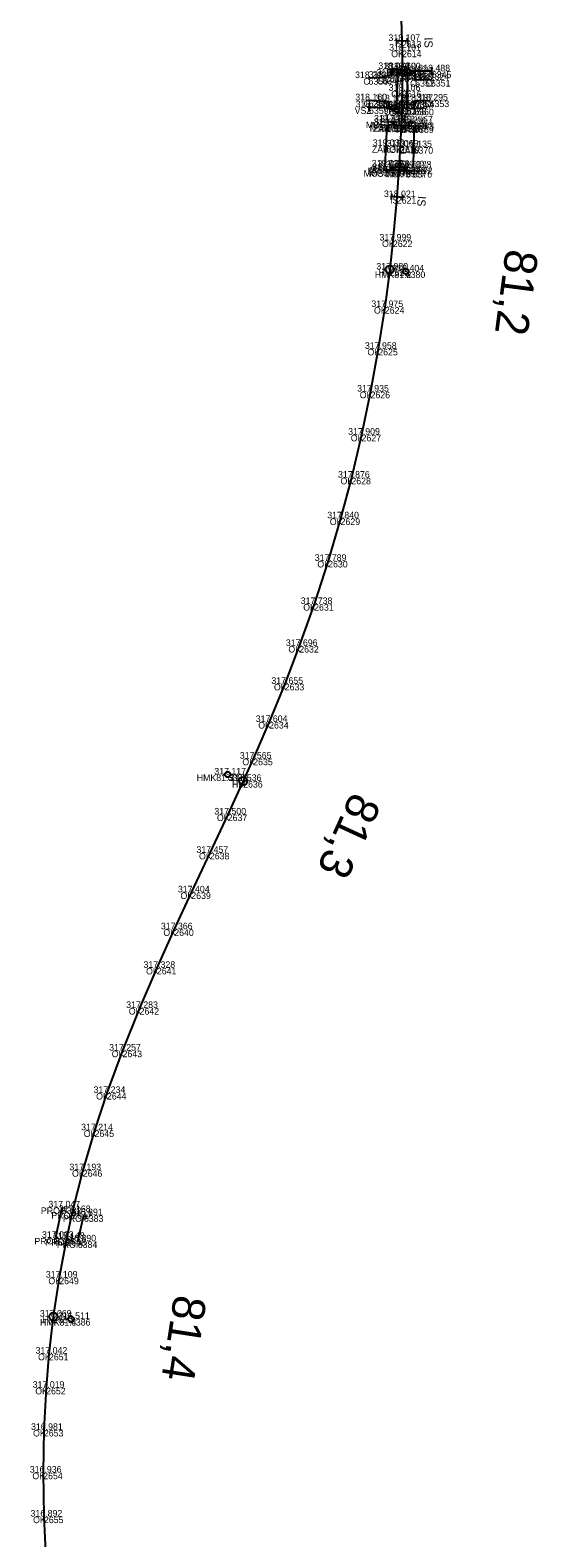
# Model space of a CAD drawing. Extents: x -621782 to -610392, y -1141853 to -1122321.
# Drawn here: x -613895.7 to -613802.8, y -1131273.8 to -1130998.2 of the extents above; entities that cross this region are included whole.
import ezdxf

# ---------------------------------------------------------------- set-up
doc = ezdxf.new("R2010")
doc.units = 0
for name, color, linetype in [('Vrstva 1', 7, 'Continuous'), ('Vrstva 17', 7, 'Continuous'), ('Vrstva 18', 7, 'Continuous'), ('Vrstva 19', 7, 'Continuous'), ('Vrstva 3', 7, 'Continuous'), ('Vrstva 4', 7, 'Continuous'), ('Vrstva 51', 7, 'Continuous'), ('Vrstva 60', 7, 'Continuous'), ('Vrstva 61', 7, 'Continuous'), ('Vrstva 62', 7, 'Continuous'), ('Vrstva 7', 7, 'Continuous')]:
    doc.layers.add(name, color=color, linetype=linetype)

msp = doc.modelspace()

# ---------------------------------------------------------------- linework, layer by layer
at = {"layer": 'Vrstva 1'}
msp.add_lwpolyline([(-613827.82, -1130996.25), (-613827.71, -1131000.22), (-613827.67, -1131001.98), (-613827.63, -1131005.39), (-613827.67, -1131009.32), (-613827.73, -1131012.39), (-613827.84, -1131015.6), (-613828.02, -1131019.5), (-613828.24, -1131023.38), (-613828.63, -1131028.75), (-613829.34, -1131036.69), (-613829.92, -1131041.99), (-613830.82, -1131048.85), (-613832.02, -1131056.48), (-613833.43, -1131064.3), (-613835.07, -1131072.18), (-613836.94, -1131080.04), (-613838.91, -1131087.47), (-613841.19, -1131095.24), (-613843.76, -1131103.13), (-613846.48, -1131110.79), (-613849.13, -1131117.71), (-613851.99, -1131124.68), (-613854.9, -1131131.39), (-613856.74, -1131135.47), (-613859.56, -1131141.59), (-613862.83, -1131148.6), (-613866.23, -1131155.83), (-613869.35, -1131162.58), (-613872.53, -1131169.62), (-613875.69, -1131176.96), (-613878.81, -1131184.75), (-613881.66, -1131192.49), (-613883.93, -1131199.32), (-613886.08, -1131206.6), (-613888.01, -1131214.26), (-613889.08, -1131219.17), (-613890.39, -1131226.24), (-613891.49, -1131233.37), (-613892.27, -1131240.14), (-613892.79, -1131246.37), (-613893.2, -1131254.07), (-613893.33, -1131261.88), (-613893.19, -1131269.91), (-613892.85, -1131277.7)], dxfattribs=at)
at = {"layer": 'Vrstva 17'}
for points in [[(-613830.76, -1131023.15), (-613830.58, -1131019.41), (-613830.41, -1131015.61)], [(-613825.46, -1131015.82), (-613825.55, -1131019.62), (-613825.65, -1131023.34)]]:
    msp.add_lwpolyline(points, dxfattribs=at)
at = {"layer": 'Vrstva 18'}
for points in [[(-613825.4, -1131015.14), (-613826.54, -1131015.12), (-613826.58, -1131015.74), (-613829.27, -1131015.62), (-613829.25, -1131015.02), (-613830.34, -1131014.94)], [(-613830.76, -1131023.82), (-613829.66, -1131023.84), (-613829.64, -1131023.24), (-613826.93, -1131023.29), (-613826.94, -1131023.94), (-613825.74, -1131023.97)]]:
    msp.add_lwpolyline(points, dxfattribs=at)
at = {"layer": 'Vrstva 19'}
for p, q in [((-613889.92, -1131213.41), (-613891.1, -1131218.97)), ((-613887, -1131219.62), (-613885.88, -1131214.85))]:
    msp.add_line(p, q, dxfattribs=at)
at = {"layer": 'Vrstva 3'}
for p, q in [((-613828.72, -1130999.74), (-613828.7, -1131000.74)), ((-613826.71, -1131000.2), (-613828.71, -1131000.24)), ((-613826.72, -1130999.7), (-613826.7, -1131000.7)), ((-613829.58, -1131028.16), (-613829.67, -1131029.16)), ((-613827.63, -1131028.84), (-613829.62, -1131028.66)), ((-613827.59, -1131028.34), (-613827.67, -1131029.34))]:
    msp.add_line(p, q, dxfattribs=at)
at = {"layer": 'Vrstva 4'}
for p, q in [((-613826.9, -1131005.92), (-613827.24, -1131005.57)), ((-613822.24, -1131006.53), (-613822.22, -1131004.98)), ((-613833.68, -1131011.57), (-613833.74, -1131013.12)), ((-613829.04, -1131012.3), (-613828.71, -1131012.66))]:
    msp.add_line(p, q, dxfattribs=at)
for points in [[(-613822.23, -1131005.76), (-613825.71, -1131005.72), (-613827.73, -1131006.69), (-613827.71, -1131004.69), (-613825.71, -1131005.72)], [(-613827.63, -1131005.39), (-613827.67, -1131009.32), (-613827.73, -1131012.39)], [(-613833.71, -1131012.34), (-613830.24, -1131012.46), (-613828.2, -1131011.55), (-613828.26, -1131013.55), (-613830.24, -1131012.46)]]:
    msp.add_lwpolyline(points, dxfattribs=at)
for centre in [(-613827.07, -1131005.74), (-613828.88, -1131012.48)]:
    msp.add_circle(centre, 0.248, dxfattribs=at)
at = {"layer": 'Vrstva 51'}
for points in [[(-613833.77, -1131011.06), (-613830.13, -1131011.25), (-613830.03, -1131012.58), (-613828.63, -1131012.42), (-613828.47, -1131005.37), (-613829.57, -1131005.35), (-613829.89, -1131006.55), (-613831.31, -1131006.92), (-613833.81, -1131007)], [(-613822.39, -1131007.34), (-613825.27, -1131007.36), (-613825.25, -1131006.16), (-613826.75, -1131006), (-613826.78, -1131012.49), (-613825.43, -1131012.59), (-613825.36, -1131011.18), (-613822.62, -1131011.1)]]:
    msp.add_lwpolyline(points, dxfattribs=at)
at = {"layer": 'Vrstva 60'}
for p, q in [((-613827.71, -1131000.22), (-613827.71, -1131000.22)), ((-613827.67, -1131001.98), (-613827.67, -1131001.98)), ((-613831.31, -1131006.92), (-613831.31, -1131006.92)), ((-613829.89, -1131006.55), (-613829.89, -1131006.55)), ((-613829.57, -1131005.35), (-613829.57, -1131005.35)), ((-613828.47, -1131005.37), (-613828.47, -1131005.37)), ((-613827.63, -1131005.39), (-613827.63, -1131005.39)), ((-613826.75, -1131006), (-613826.75, -1131006)), ((-613825.25, -1131006.16), (-613825.25, -1131006.16)), ((-613822.23, -1131005.76), (-613822.23, -1131005.76)), ((-613833.81, -1131007), (-613833.81, -1131007)), ((-613827.67, -1131009.32), (-613827.67, -1131009.32)), ((-613825.27, -1131007.36), (-613825.27, -1131007.36)), ((-613822.39, -1131007.34), (-613822.39, -1131007.34)), ((-613833.77, -1131011.06), (-613833.77, -1131011.06)), ((-613833.71, -1131012.34), (-613833.71, -1131012.34)), ((-613830.13, -1131011.25), (-613830.13, -1131011.25)), ((-613828.63, -1131012.42), (-613828.63, -1131012.42)), ((-613827.73, -1131012.39), (-613827.73, -1131012.39)), ((-613826.78, -1131012.49), (-613826.78, -1131012.49)), ((-613825.36, -1131011.18), (-613825.36, -1131011.18)), ((-613822.62, -1131011.1), (-613822.62, -1131011.1)), ((-613830.34, -1131014.94), (-613830.34, -1131014.94)), ((-613830.03, -1131012.58), (-613830.03, -1131012.58)), ((-613829.25, -1131015.02), (-613829.25, -1131015.02)), ((-613826.54, -1131015.12), (-613826.54, -1131015.12)), ((-613825.43, -1131012.59), (-613825.43, -1131012.59)), ((-613825.4, -1131015.14), (-613825.4, -1131015.14)), ((-613830.41, -1131015.61), (-613830.41, -1131015.61)), ((-613829.27, -1131015.62), (-613829.27, -1131015.62)), ((-613827.84, -1131015.6), (-613827.84, -1131015.6)), ((-613826.58, -1131015.74), (-613826.58, -1131015.74)), ((-613825.46, -1131015.82), (-613825.46, -1131015.82)), ((-613830.58, -1131019.41), (-613830.58, -1131019.41)), ((-613828.02, -1131019.5), (-613828.02, -1131019.5)), ((-613825.55, -1131019.62), (-613825.55, -1131019.62)), ((-613830.76, -1131023.15), (-613830.76, -1131023.15)), ((-613829.64, -1131023.24), (-613829.64, -1131023.24)), ((-613828.24, -1131023.38), (-613828.24, -1131023.38)), ((-613826.93, -1131023.29), (-613826.93, -1131023.29)), ((-613825.65, -1131023.34), (-613825.65, -1131023.34)), ((-613830.76, -1131023.82), (-613830.76, -1131023.82)), ((-613829.66, -1131023.84), (-613829.66, -1131023.84)), ((-613826.94, -1131023.94), (-613826.94, -1131023.94)), ((-613825.74, -1131023.97), (-613825.74, -1131023.97)), ((-613828.63, -1131028.75), (-613828.63, -1131028.75)), ((-613829.34, -1131036.69), (-613829.34, -1131036.69)), ((-613829.92, -1131041.99), (-613829.92, -1131041.99)), ((-613826.99, -1131042.34), (-613826.99, -1131042.34)), ((-613830.82, -1131048.85), (-613830.82, -1131048.85)), ((-613832.02, -1131056.48), (-613832.02, -1131056.48)), ((-613833.43, -1131064.3), (-613833.43, -1131064.3)), ((-613835.07, -1131072.18), (-613835.07, -1131072.18)), ((-613836.94, -1131080.04), (-613836.94, -1131080.04)), ((-613838.91, -1131087.47), (-613838.91, -1131087.47)), ((-613841.19, -1131095.24), (-613841.19, -1131095.24)), ((-613843.76, -1131103.13), (-613843.76, -1131103.13)), ((-613846.48, -1131110.79), (-613846.48, -1131110.79)), ((-613849.13, -1131117.71), (-613849.13, -1131117.71)), ((-613851.99, -1131124.68), (-613851.99, -1131124.68)), ((-613854.9, -1131131.39), (-613854.9, -1131131.39)), ((-613859.57, -1131134.28), (-613859.57, -1131134.28)), ((-613856.74, -1131135.47), (-613856.74, -1131135.47)), ((-613859.56, -1131141.59), (-613859.56, -1131141.59)), ((-613862.83, -1131148.6), (-613862.83, -1131148.6)), ((-613866.23, -1131155.83), (-613866.23, -1131155.83)), ((-613869.35, -1131162.58), (-613869.35, -1131162.58)), ((-613872.53, -1131169.62), (-613872.53, -1131169.62)), ((-613875.69, -1131176.96), (-613875.69, -1131176.96)), ((-613878.81, -1131184.75), (-613878.81, -1131184.75)), ((-613881.66, -1131192.49), (-613881.66, -1131192.49)), ((-613883.93, -1131199.32), (-613883.93, -1131199.32)), ((-613886.08, -1131206.6), (-613886.08, -1131206.6)), ((-613889.92, -1131213.41), (-613889.92, -1131213.41)), ((-613888.01, -1131214.26), (-613888.01, -1131214.26)), ((-613885.88, -1131214.85), (-613885.88, -1131214.85)), ((-613891.1, -1131218.97), (-613891.1, -1131218.97)), ((-613889.08, -1131219.17), (-613889.08, -1131219.17)), ((-613887, -1131219.62), (-613887, -1131219.62)), ((-613890.39, -1131226.24), (-613890.39, -1131226.24)), ((-613891.49, -1131233.37), (-613891.49, -1131233.37)), ((-613888.25, -1131233.8), (-613888.25, -1131233.8)), ((-613892.27, -1131240.14), (-613892.27, -1131240.14)), ((-613892.79, -1131246.37), (-613892.79, -1131246.37)), ((-613893.2, -1131254.07), (-613893.2, -1131254.07)), ((-613893.33, -1131261.88), (-613893.33, -1131261.88)), ((-613893.19, -1131269.91), (-613893.19, -1131269.91))]:
    msp.add_line(p, q, dxfattribs=at)
at = {"layer": 'Vrstva 7'}
for p, q in [((-613826.99, -1131042.29), (-613827, -1131042.39)), ((-613859.55, -1131134.24), (-613859.59, -1131134.33)), ((-613888.24, -1131233.75), (-613888.26, -1131233.85))]:
    msp.add_line(p, q, dxfattribs=at)
for centre, radius in [((-613829.92, -1131041.99), 0.75), ((-613826.99, -1131042.34), 0.5), ((-613859.57, -1131134.28), 0.5), ((-613856.74, -1131135.47), 0.75), ((-613891.49, -1131233.37), 0.75), ((-613888.25, -1131233.8), 0.5)]:
    msp.add_circle(centre, radius, dxfattribs=at)

# ---------------------------------------------------------------- texts
at = {"layer": 'Vrstva 3'}
for rotation, p in [(271.1711, (-613823.6, -1130999.58)), (264.8479, (-613824.75, -1131028.5))]:
    msp.add_text('IS', height=1.5, rotation=rotation, dxfattribs=at).set_placement(p)
at = {"layer": 'Vrstva 60'}
for s, p in [('2613', (-613827.71, -1131001.42)), ('2614', (-613827.67, -1131003.18)), ('6350', (-613833.81, -1131008.2)), ('6349', (-613831.31, -1131008.11)), ('6348', (-613829.89, -1131007.75)), ('6343', (-613829.57, -1131006.55)), ('6344', (-613828.47, -1131006.57)), ('2615', (-613827.63, -1131006.59)), ('6346', (-613826.75, -1131007.2)), ('6347', (-613825.25, -1131007.36)), ('6345', (-613822.23, -1131006.96)), ('2616', (-613827.67, -1131010.52)), ('6352', (-613825.27, -1131008.56)), ('6351', (-613822.39, -1131008.54)), ('6355', (-613833.77, -1131012.26)), ('6359', (-613833.71, -1131013.54)), ('6356', (-613830.13, -1131012.45)), ('6357', (-613828.63, -1131013.62)), ('2617', (-613827.73, -1131013.59)), ('6358', (-613826.78, -1131013.69)), ('6354', (-613825.36, -1131012.38)), ('6353', (-613822.62, -1131012.3)), ('6362', (-613830.34, -1131016.14)), ('6361', (-613830.03, -1131013.78)), ('6364', (-613829.25, -1131016.22)), ('6365', (-613826.54, -1131016.32)), ('6360', (-613825.43, -1131013.79)), ('6363', (-613825.4, -1131016.34)), ('6368', (-613830.41, -1131016.81)), ('6366', (-613829.27, -1131016.82)), ('2618', (-613827.84, -1131016.8)), ('6367', (-613826.58, -1131016.94)), ('6369', (-613825.46, -1131017.02)), ('6371', (-613830.58, -1131020.61)), ('2619', (-613828.02, -1131020.7)), ('6370', (-613825.55, -1131020.82)), ('6374', (-613830.76, -1131024.35)), ('6375', (-613829.64, -1131024.44)), ('2620', (-613828.24, -1131024.58)), ('6373', (-613826.93, -1131024.49)), ('6372', (-613825.65, -1131024.54)), ('6379', (-613830.76, -1131025.02)), ('6378', (-613829.66, -1131025.04)), ('6377', (-613826.94, -1131025.14)), ('6376', (-613825.74, -1131025.17)), ('2621', (-613828.63, -1131029.95)), ('2622', (-613829.34, -1131037.89)), ('2623', (-613829.92, -1131043.19)), ('6380', (-613826.99, -1131043.54)), ('2624', (-613830.82, -1131050.05)), ('2625', (-613832.02, -1131057.68)), ('2626', (-613833.43, -1131065.51)), ('2627', (-613835.07, -1131073.38)), ('2628', (-613836.94, -1131081.24)), ('2629', (-613838.91, -1131088.67)), ('2630', (-613841.19, -1131096.44)), ('2631', (-613843.76, -1131104.33)), ('2632', (-613846.48, -1131111.99)), ('2633', (-613849.13, -1131118.91)), ('2634', (-613851.99, -1131125.88)), ('2635', (-613854.9, -1131132.59)), ('6381', (-613859.57, -1131135.48)), ('2636', (-613856.74, -1131136.67)), ('2637', (-613859.56, -1131142.79)), ('2638', (-613862.83, -1131149.8)), ('2639', (-613866.23, -1131157.03)), ('2640', (-613869.35, -1131163.78)), ('2641', (-613872.53, -1131170.82)), ('2642', (-613875.69, -1131178.16)), ('2643', (-613878.81, -1131185.95)), ('2644', (-613881.66, -1131193.69)), ('2645', (-613883.93, -1131200.52)), ('2646', (-613886.08, -1131207.8)), ('6382', (-613889.92, -1131214.61)), ('2647', (-613888.01, -1131215.46)), ('6383', (-613885.88, -1131216.05)), ('6385', (-613891.1, -1131220.17)), ('2648', (-613889.08, -1131220.37)), ('6384', (-613887, -1131220.82)), ('2649', (-613890.39, -1131227.44)), ('2650', (-613891.49, -1131234.57)), ('6386', (-613888.25, -1131235)), ('2651', (-613892.27, -1131241.34)), ('2652', (-613892.79, -1131247.57)), ('2653', (-613893.2, -1131255.27)), ('2654', (-613893.33, -1131263.08)), ('2655', (-613893.19, -1131271.11))]:
    msp.add_text(s, height=1.2, dxfattribs=at).set_placement(p)
at = {"layer": 'Vrstva 61'}
for s, p in [('318.107', (-613830.16, -1131000.22)), ('318.101', (-613830.03, -1131001.98)), ('318.072', (-613832.01, -1131005.35)), ('318.060', (-613830.92, -1131005.37)), ('318.100', (-613830.08, -1131005.39)), ('318.203', (-613836.27, -1131007)), ('318.189', (-613833.77, -1131006.92)), ('318.149', (-613832.35, -1131006.55)), ('318.140', (-613829.2, -1131006)), ('318.219', (-613827.72, -1131007.36)), ('318.233', (-613827.7, -1131006.16)), ('318.324', (-613824.84, -1131007.34)), ('318.488', (-613824.69, -1131005.76)), ('318.106', (-613830.12, -1131009.32)), ('318.160', (-613836.22, -1131011.06)), ('318.246', (-613836.17, -1131012.34)), ('318.102', (-613832.58, -1131011.25)), ('318.086', (-613832.48, -1131012.58)), ('318.085', (-613831.08, -1131012.42)), ('318.087', (-613830.19, -1131012.39)), ('318.123', (-613829.23, -1131012.49)), ('318.107', (-613827.88, -1131012.59)), ('318.187', (-613827.81, -1131011.18)), ('318.295', (-613825.08, -1131011.1)), ('319.039', (-613832.86, -1131015.61)), ('317.878', (-613832.8, -1131014.94)), ('317.880', (-613831.7, -1131015.02)), ('317.871', (-613831.62, -1131015.62)), ('318.074', (-613830.29, -1131015.6)), ('317.946', (-613829.03, -1131015.74)), ('317.961', (-613828.9, -1131015.12)), ('319.164', (-613827.91, -1131015.82)), ('317.957', (-613827.85, -1131015.14)), ('319.030', (-613833.04, -1131019.41)), ('318.069', (-613830.48, -1131019.5)), ('319.135', (-613828.01, -1131019.62)), ('319.032', (-613833.21, -1131023.15)), ('317.851', (-613833.11, -1131023.82)), ('317.852', (-613832.1, -1131023.84)), ('317.858', (-613832.09, -1131023.24)), ('318.046', (-613830.69, -1131023.38)), ('317.920', (-613829.39, -1131023.94)), ('317.949', (-613829.38, -1131023.29)), ('317.925', (-613828.2, -1131023.97)), ('319.128', (-613828.1, -1131023.34)), ('318.021', (-613830.98, -1131028.75)), ('317.999', (-613831.8, -1131036.69)), ('317.980', (-613832.37, -1131041.99)), ('318.404', (-613829.44, -1131042.34)), ('317.975', (-613833.28, -1131048.85)), ('317.958', (-613834.47, -1131056.48)), ('317.935', (-613835.89, -1131064.3)), ('317.909', (-613837.53, -1131072.18)), ('317.876', (-613839.39, -1131080.04)), ('317.840', (-613841.36, -1131087.47)), ('317.789', (-613843.64, -1131095.24)), ('317.738', (-613846.22, -1131103.13)), ('317.696', (-613848.93, -1131110.79)), ('317.655', (-613851.58, -1131117.71)), ('317.604', (-613854.44, -1131124.68)), ('317.565', (-613857.36, -1131131.39)), ('317.117', (-613862.02, -1131134.28)), ('317.536', (-613859.2, -1131135.47)), ('317.500', (-613862.01, -1131141.59)), ('317.457', (-613865.29, -1131148.6)), ('317.404', (-613868.68, -1131155.83)), ('317.366', (-613871.8, -1131162.58)), ('317.328', (-613874.98, -1131169.62)), ('317.283', (-613878.14, -1131176.96)), ('317.257', (-613881.26, -1131184.75)), ('317.234', (-613884.11, -1131192.49)), ('317.214', (-613886.38, -1131199.32)), ('317.193', (-613888.53, -1131206.6)), ('317.047', (-613892.37, -1131213.41)), ('317.168', (-613890.46, -1131214.26)), ('316.891', (-613888.24, -1131214.85)), ('317.003', (-613893.55, -1131218.97)), ('317.148', (-613891.53, -1131219.17)), ('316.890', (-613889.45, -1131219.62)), ('317.109', (-613892.85, -1131226.24)), ('317.069', (-613893.94, -1131233.37)), ('316.511', (-613890.61, -1131233.8)), ('317.042', (-613894.72, -1131240.14)), ('317.019', (-613895.24, -1131246.37)), ('316.981', (-613895.55, -1131254.07)), ('316.936', (-613895.78, -1131261.88)), ('316.892', (-613895.64, -1131269.91))]:
    msp.add_text(s, height=1.2, dxfattribs=at).set_placement(p)
at = {"layer": 'Vrstva 62'}
for s, p in [('IS', (-613828.94, -1131001.42)), ('OK', (-613829.66, -1131003.18)), ('C', (-613834.75, -1131008.2)), ('C', (-613832.25, -1131008.11)), ('C', (-613830.83, -1131007.75)), ('C', (-613830.5, -1131006.55)), ('PRJ', (-613830.12, -1131006.59)), ('C', (-613829.41, -1131006.57)), ('C', (-613827.69, -1131007.2)), ('C', (-613826.18, -1131007.36)), ('VSZ', (-613824.87, -1131006.96)), ('OK', (-613829.65, -1131010.52)), ('C', (-613826.2, -1131008.56)), ('C', (-613823.32, -1131008.54)), ('VSZ', (-613836.35, -1131013.54)), ('C', (-613834.7, -1131012.26)), ('C', (-613831.07, -1131012.45)), ('PRJ', (-613830.22, -1131013.59)), ('C', (-613829.56, -1131013.62)), ('C', (-613827.71, -1131013.69)), ('C', (-613826.29, -1131012.38)), ('C', (-613823.56, -1131012.3)), ('MOST', (-613834.29, -1131016.14)), ('MOST', (-613833.19, -1131016.22)), ('C', (-613830.96, -1131013.78)), ('MOST', (-613830.49, -1131016.32)), ('MOST', (-613829.34, -1131016.34)), ('C', (-613826.36, -1131013.79)), ('MOSTBS', (-613833.58, -1131016.8)), ('MOST', (-613833.21, -1131016.82)), ('ZAB', (-613833.01, -1131016.81)), ('MOST', (-613830.52, -1131016.94)), ('ZAB', (-613828.06, -1131017.02)), ('ZAB', (-613833.19, -1131020.61)), ('OK', (-613830.01, -1131020.7)), ('ZAB', (-613828.15, -1131020.82)), ('MOSTBS', (-613833.97, -1131024.58)), ('MOST', (-613833.58, -1131024.44)), ('ZAB', (-613833.36, -1131024.35)), ('MOST', (-613830.87, -1131024.49)), ('ZAB', (-613828.25, -1131024.54)), ('MOST', (-613834.7, -1131025.02)), ('MOST', (-613833.6, -1131025.04)), ('MOST', (-613830.88, -1131025.14)), ('MOST', (-613829.69, -1131025.17)), ('IS', (-613829.85, -1131029.95)), ('OK', (-613831.33, -1131037.89)), ('HMK81.2', (-613832.65, -1131043.54)), ('HM', (-613831.96, -1131043.19)), ('OK', (-613832.81, -1131050.05)), ('OK', (-613834, -1131057.68)), ('OK', (-613835.41, -1131065.51)), ('OK', (-613837.06, -1131073.38)), ('OK', (-613838.93, -1131081.24)), ('OK', (-613840.89, -1131088.67)), ('OK', (-613843.17, -1131096.44)), ('OK', (-613845.75, -1131104.33)), ('OK', (-613848.47, -1131111.99)), ('OK', (-613851.11, -1131118.91)), ('OK', (-613853.98, -1131125.88)), ('OK', (-613856.89, -1131132.59)), ('HMK81.3', (-613865.23, -1131135.48)), ('HM', (-613858.78, -1131136.67)), ('OK', (-613861.54, -1131142.79)), ('OK', (-613864.82, -1131149.8)), ('OK', (-613868.21, -1131157.03)), ('OK', (-613871.34, -1131163.78)), ('OK', (-613874.51, -1131170.82)), ('OK', (-613877.67, -1131178.16)), ('OK', (-613880.79, -1131185.95)), ('OK', (-613883.64, -1131193.69)), ('OK', (-613885.91, -1131200.52)), ('OK', (-613888.06, -1131207.8)), ('PROP', (-613893.75, -1131214.61)), ('PROP', (-613891.84, -1131215.46)), ('PROP', (-613889.72, -1131216.05)), ('PROP', (-613894.93, -1131220.17)), ('PROP', (-613892.91, -1131220.37)), ('PROP', (-613890.83, -1131220.82)), ('OK', (-613892.38, -1131227.44)), ('HMK81.4', (-613893.91, -1131235)), ('HM', (-613893.52, -1131234.57)), ('OK', (-613894.26, -1131241.34)), ('OK', (-613894.78, -1131247.57)), ('OK', (-613895.18, -1131255.27)), ('OK', (-613895.31, -1131263.08)), ('OK', (-613895.18, -1131271.11))]:
    msp.add_text(s, height=1.2, dxfattribs=at).set_placement(p)
at = {"layer": 'Vrstva 7'}
for s, rotation, p in [('81,2', 262.5461, (-613808.67, -1131038.07)), ('81,3', 245.3365, (-613836.81, -1131137.23)), ('81,4', 261.2659, (-613869.34, -1131229.18))]:
    msp.add_text(s, height=6, rotation=rotation, dxfattribs=at).set_placement(p)

doc.saveas('drawing.dxf')
